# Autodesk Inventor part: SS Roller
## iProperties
Shininess: 64.0
Length Units: 11272
Angle Units: 11279
Time Units: 11290
Mass Units: 11286
Length Display Precision: 3
Angle Display Precision: 2
Compacted: True
Part Number: SS Roller
Document SubType Name: Modeling
Created: 2003-09
Designer: jpittman
Manufacturer: Standard
Standards Organization: Custom
Density: 0.0
Volumn: 0.0
Area: 0.0
PropertySet Name: Model Information
Control State: 0
Master: False
Checked Out: False
Author: jpittman
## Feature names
1. Extrusion1
